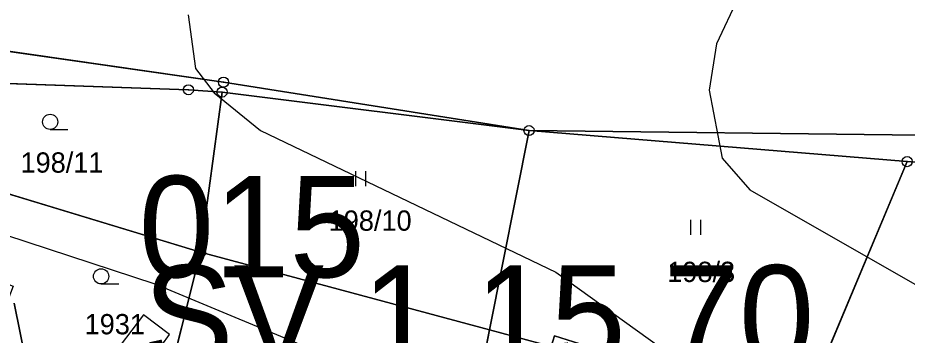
# Model space of a CAD drawing. Extents: x -706130 to -698555, y -971544 to -967260.
# Drawn here: x -703723 to -703635.3, y -970324.1 to -970292.8 of the extents above; entities that cross this region are included whole.
import ezdxf

# ---------------------------------------------------------------- set-up
doc = ezdxf.new("R2010")
doc.units = 0
for name, color, linetype in [('_Doplněk budov pro zastavěnost', 7, 'Continuous'), ('BPEJ hranice S', 7, 'Continuous'), ('Docházková izochrona - VLAK N', 7, 'Continuous'), ('Hranice intravilán', 7, 'Continuous'), ('KN_Hranice_parcel', 7, 'Continuous'), ('KN_Parcelni cisla', 7, 'Continuous'), ('KN_Polygon parcely', 7, 'Continuous'), ('KN_POZEMKY_10_LESNI POZEMEK', 7, 'Continuous'), ('KN_POZEMKY_14_OSTATNI PLOCHA', 7, 'Continuous'), ('KN_POZEMKY_5_ZAHRADA', 7, 'Continuous'), ('KN_POZEMKY_7_TTP', 7, 'Continuous'), ('KN_VYUZITI_17_ostatni plocha_ostatni komunikace', 7, 'Continuous'), ('KN_Značky bodu BP', 7, 'Continuous'), ('KN_Značky kultur', 7, 'Continuous'), ('Plochy lesní všeobecné S', 7, 'Continuous'), ('Plochy smíšené nezastavěného území všeobecné S', 7, 'Continuous'), ('Plochy smíšené obytné venkovské S', 7, 'Continuous'), ('Regulační bloky v krajině S', 7, 'Continuous'), ('Regulační bloky zastavěné S', 7, 'Continuous'), ('Regulační bloky_číslo S NEZAPINAT', 7, 'Continuous'), ('Regulační kódy zastavěné S', 7, 'Continuous'), ('VÝŠKOPIS_vrstevnice hlavní', 7, 'Continuous'), ('Zastavene uzemi N', 7, 'Continuous'), ('Zastavene uzemi plochy N', 7, 'Continuous')]:
    doc.layers.add(name, color=color, linetype=linetype)

msp = doc.modelspace()

# ---------------------------------------------------------------- linework, layer by layer
at = {"layer": '_Doplněk budov pro zastavěnost'}
msp.add_line((-703711.358, -970328.612), (-703708.082, -970324.03), dxfattribs=at)
msp.add_lwpolyline([(-703708.082, -970324.03), (-703710.648, -970322.082), (-703714.088, -970326.612)], dxfattribs=at)
at = {"layer": 'BPEJ hranice S'}
for points in [[(-703738.09, -970298.78), (-703706.21, -970299.88), (-703702.89, -970300.11), (-703672.63, -970303.91), (-703635.35, -970306.97), (-703646.15, -970332.73), (-703632.252, -970340.643)], [(-703632.252, -970340.643), (-703646.15, -970332.73), (-703635.35, -970306.97), (-703672.63, -970303.91), (-703702.89, -970300.11), (-703706.21, -970299.88), (-703738.09, -970298.78)], [(-703724.808, -970348.497), (-703721.895, -970339.494), (-703722.086, -970331.681), (-703722.192, -970327.348), (-703722.205, -970326.79), (-703723.373, -970320.95)], [(-703723.373, -970320.95), (-703722.205, -970326.79), (-703722.192, -970327.348), (-703722.086, -970331.681), (-703721.895, -970339.494), (-703724.808, -970348.497)]]:
    msp.add_lwpolyline(points, dxfattribs=at)
at = {"layer": 'Docházková izochrona - VLAK N'}
msp.add_circle((-704165.451, -969778.767), 800, dxfattribs=at)
at = {"layer": 'Hranice intravilán'}
msp.add_lwpolyline([(-703631.45, -970341.1), (-703646.15, -970332.73), (-703648.8, -970331.89), (-703654.16, -970330.19), (-703653.88, -970329.3), (-703670.11, -970324.16), (-703670.44, -970325.21), (-703676.52, -970323.58), (-703679.36, -970337.91), (-703708.75, -970330.82), (-703705.03, -970315.92), (-703739.49, -970305.44), (-703738.09, -970298.78), (-703775.52, -970299.64)], dxfattribs=at)
at = {"layer": 'KN_Hranice_parcel'}
for p, q in [((-703672.63, -970303.91), (-703702.74, -970299.14)), ((-703702.89, -970300.11), (-703705.03, -970315.92)), ((-703672.63, -970303.91), (-703702.89, -970300.11)), ((-703672.63, -970303.91), (-703676.52, -970323.58)), ((-703635.35, -970306.97), (-703672.63, -970303.91)), ((-703739.49, -970305.44), (-703705.03, -970315.92)), ((-703646.15, -970332.73), (-703635.35, -970306.97)), ((-703705.03, -970315.92), (-703708.75, -970330.82)), ((-703705.03, -970315.92), (-703676.52, -970323.58)), ((-703676.52, -970323.58), (-703679.36, -970337.91)), ((-703676.52, -970323.58), (-703670.44, -970325.21))]:
    msp.add_line(p, q, dxfattribs=at)
for points in [[(-703702.74, -970299.14), (-703733.34, -970294.74), (-703763.35, -970295.57), (-703799.54, -970296.87)], [(-703702.89, -970300.11), (-703706.21, -970299.88), (-703738.09, -970298.78)], [(-703623.56, -970304.51), (-703634.06, -970304.37), (-703672.63, -970303.91)], [(-703526.62, -970376.37), (-703586.2, -970324.53), (-703627.08, -970307.65), (-703635.35, -970306.97)]]:
    msp.add_lwpolyline(points, dxfattribs=at)
at = {"layer": 'KN_Polygon parcely'}
for points in [[(-703575.83, -970307.17), (-703543.88, -970308.96), (-703519.13, -970313.02), (-703534.02, -970307.63), (-703565.14, -970278.41), (-703570.06, -970274.88), (-703590.14, -970267.18), (-703599.73, -970265.63), (-703609.71, -970264.02), (-703624.74, -970265.74), (-703731.89, -970278.02), (-703810.39, -970283.01), (-703832.17, -970298.91), (-703799.54, -970296.87), (-703763.35, -970295.57), (-703733.34, -970294.74), (-703702.74, -970299.14), (-703672.63, -970303.91), (-703634.06, -970304.37), (-703623.56, -970304.51)], [(-703832.17, -970298.91), (-703833.56, -970299.93), (-703832.7, -970301.24), (-703809.34, -970300.42), (-703775.52, -970299.64), (-703738.09, -970298.78), (-703706.21, -970299.88), (-703702.89, -970300.11), (-703672.63, -970303.91), (-703702.74, -970299.14), (-703733.34, -970294.74), (-703763.35, -970295.57), (-703799.54, -970296.87)], [(-703739.49, -970305.44), (-703705.03, -970315.92), (-703702.89, -970300.11), (-703706.21, -970299.88), (-703738.09, -970298.78)], [(-703702.89, -970300.11), (-703705.03, -970315.92), (-703676.52, -970323.58), (-703672.63, -970303.91)], [(-703646.15, -970332.73), (-703635.35, -970306.97), (-703672.63, -970303.91), (-703676.52, -970323.58), (-703670.44, -970325.21), (-703670.11, -970324.16), (-703653.88, -970329.3), (-703654.16, -970330.19), (-703648.8, -970331.89)], [(-703634.06, -970304.37), (-703672.63, -970303.91), (-703635.35, -970306.97), (-703627.08, -970307.65), (-703586.2, -970324.53), (-703526.62, -970376.37), (-703520.6, -970377.03), (-703567.84, -970335.32), (-703584.36, -970321.95), (-703623.56, -970304.51)], [(-703708.75, -970330.82), (-703705.03, -970315.92), (-703739.49, -970305.44), (-703743.13, -970318.6), (-703744, -970321.72), (-703741.07, -970322.48), (-703739.71, -970319.1), (-703737.59, -970313.85), (-703723.5, -970319.27), (-703725.62, -970324.78), (-703726.21, -970326.31)], [(-703625.56, -970327.91), (-703593.92, -970335.61), (-703602.16, -970353.21), (-703568.92, -970363.91), (-703550.58, -970370.54), (-703536.13, -970374.49), (-703526.62, -970376.37), (-703586.2, -970324.53), (-703627.08, -970307.65), (-703635.35, -970306.97), (-703646.15, -970332.73), (-703631.45, -970341.1)], [(-703708.75, -970330.82), (-703679.36, -970337.91), (-703676.52, -970323.58), (-703705.03, -970315.92)], [(-703679.36, -970337.91), (-703648.37, -970348.91), (-703639.36, -970354.95), (-703637.01, -970347.57), (-703646.15, -970332.73), (-703648.8, -970331.89), (-703649.55, -970334.26), (-703651.62, -970340.78), (-703673.2, -970333.94), (-703670.44, -970325.21), (-703676.52, -970323.58)]]:
    msp.add_lwpolyline(points, close=True, dxfattribs=at)
at = {"layer": 'KN_POZEMKY_10_LESNI POZEMEK'}
for p, q in [((-703733.34, -970294.74), (-703702.74, -970299.14)), ((-703702.74, -970299.14), (-703733.34, -970294.74)), ((-703706.21, -970299.88), (-703738.09, -970298.78)), ((-703702.74, -970299.14), (-703672.63, -970303.91)), ((-703672.63, -970303.91), (-703702.74, -970299.14)), ((-703702.89, -970300.11), (-703706.21, -970299.88)), ((-703672.63, -970303.91), (-703702.89, -970300.11)), ((-703634.06, -970304.37), (-703672.63, -970303.91)), ((-703646.15, -970332.73), (-703635.35, -970306.97)), ((-703635.35, -970306.97), (-703627.08, -970307.65))]:
    msp.add_line(p, q, dxfattribs=at)
at = {"layer": 'KN_POZEMKY_14_OSTATNI PLOCHA'}
for p, q in [((-703635.35, -970306.97), (-703672.63, -970303.91)), ((-703672.63, -970303.91), (-703634.06, -970304.37)), ((-703627.08, -970307.65), (-703635.35, -970306.97))]:
    msp.add_line(p, q, dxfattribs=at)
at = {"layer": 'KN_POZEMKY_5_ZAHRADA'}
for p, q in [((-703738.09, -970298.78), (-703706.21, -970299.88)), ((-703706.21, -970299.88), (-703702.89, -970300.11)), ((-703702.89, -970300.11), (-703705.03, -970315.92)), ((-703705.03, -970315.92), (-703739.49, -970305.44)), ((-703739.49, -970305.44), (-703705.03, -970315.92)), ((-703705.03, -970315.92), (-703708.75, -970330.82))]:
    msp.add_line(p, q, dxfattribs=at)
at = {"layer": 'KN_POZEMKY_7_TTP'}
for p, q in [((-703705.03, -970315.92), (-703702.89, -970300.11)), ((-703702.89, -970300.11), (-703672.63, -970303.91)), ((-703672.63, -970303.91), (-703676.52, -970323.58)), ((-703676.52, -970323.58), (-703672.63, -970303.91)), ((-703672.63, -970303.91), (-703635.35, -970306.97)), ((-703635.35, -970306.97), (-703646.15, -970332.73)), ((-703708.75, -970330.82), (-703705.03, -970315.92)), ((-703676.52, -970323.58), (-703705.03, -970315.92)), ((-703705.03, -970315.92), (-703676.52, -970323.58)), ((-703679.36, -970337.91), (-703676.52, -970323.58)), ((-703676.52, -970323.58), (-703679.36, -970337.91)), ((-703676.52, -970323.58), (-703670.44, -970325.21)), ((-703670.44, -970325.21), (-703676.52, -970323.58))]:
    msp.add_line(p, q, dxfattribs=at)
at = {"layer": 'KN_VYUZITI_17_ostatni plocha_ostatni komunikace'}
for p, q in [((-703635.35, -970306.97), (-703672.63, -970303.91)), ((-703672.63, -970303.91), (-703634.06, -970304.37)), ((-703627.08, -970307.65), (-703635.35, -970306.97))]:
    msp.add_line(p, q, dxfattribs=at)
at = {"layer": 'KN_Značky bodu BP'}
for centre, radius in [((-703702.74, -970299.14), 0.5), ((-703706.21, -970299.88), 0.5), ((-703706.21, -970299.88), 0.0303), ((-703702.89, -970300.11), 0.5), ((-703702.74, -970299.14), 0.0303), ((-703702.89, -970300.11), 0.0303), ((-703672.63, -970303.91), 0.5), ((-703672.63, -970303.91), 0.0303), ((-703635.35, -970306.97), 0.5), ((-703635.35, -970306.97), 0.0303), ((-703705.03, -970315.92), 0.5), ((-703705.03, -970315.92), 0.0303)]:
    msp.add_circle(centre, radius, dxfattribs=at)
at = {"layer": 'KN_Značky kultur'}
for p, q in [((-703719.833, -970303.8), (-703718.083, -970303.8)), ((-703689.701, -970309.4), (-703689.701, -970307.9)), ((-703688.7, -970309.4), (-703688.7, -970307.9)), ((-703656.691, -970314.21), (-703656.691, -970312.71)), ((-703655.69, -970314.21), (-703655.69, -970312.71)), ((-703714.813, -970319.04), (-703713.063, -970319.04))]:
    msp.add_line(p, q, dxfattribs=at)
for centre in [(-703719.833, -970303.05), (-703714.813, -970318.29)]:
    msp.add_circle(centre, 0.75, dxfattribs=at)
at = {"layer": 'Plochy lesní všeobecné S'}
for p, q in [((-703738.09, -970298.78), (-703706.21, -970299.88)), ((-703706.21, -970299.88), (-703702.89, -970300.11)), ((-703702.89, -970300.11), (-703672.63, -970303.91)), ((-703672.63, -970303.91), (-703634.06, -970304.37)), ((-703635.35, -970306.97), (-703646.15, -970332.73)), ((-703627.08, -970307.65), (-703635.35, -970306.97))]:
    msp.add_line(p, q, dxfattribs=at)
at = {"layer": 'Plochy smíšené nezastavěného území všeobecné S'}
msp.add_line((-703635.35, -970306.97), (-703627.08, -970307.65), dxfattribs=at)
msp.add_lwpolyline([(-703623.56, -970304.51), (-703634.06, -970304.37), (-703672.63, -970303.91), (-703635.35, -970306.97)], dxfattribs=at)
at = {"layer": 'Plochy smíšené obytné venkovské S'}
for p, q in [((-703706.21, -970299.88), (-703738.09, -970298.78)), ((-703702.89, -970300.11), (-703706.21, -970299.88)), ((-703672.63, -970303.91), (-703702.89, -970300.11)), ((-703635.35, -970306.97), (-703672.63, -970303.91)), ((-703646.15, -970332.73), (-703635.35, -970306.97))]:
    msp.add_line(p, q, dxfattribs=at)
at = {"layer": 'Regulační bloky v krajině S'}
for p, q in [((-703738.09, -970298.78), (-703706.21, -970299.88)), ((-703706.21, -970299.88), (-703702.89, -970300.11)), ((-703702.89, -970300.11), (-703672.63, -970303.91)), ((-703672.63, -970303.91), (-703634.06, -970304.37)), ((-703635.35, -970306.97), (-703646.15, -970332.73)), ((-703627.08, -970307.65), (-703635.35, -970306.97)), ((-703635.35, -970306.97), (-703627.08, -970307.65))]:
    msp.add_line(p, q, dxfattribs=at)
msp.add_lwpolyline([(-703623.56, -970304.51), (-703634.06, -970304.37), (-703672.63, -970303.91), (-703635.35, -970306.97)], dxfattribs=at)
at = {"layer": 'Regulační bloky zastavěné S'}
for p, q in [((-703706.21, -970299.88), (-703738.09, -970298.78)), ((-703702.89, -970300.11), (-703706.21, -970299.88)), ((-703672.63, -970303.91), (-703702.89, -970300.11)), ((-703635.35, -970306.97), (-703672.63, -970303.91)), ((-703646.15, -970332.73), (-703635.35, -970306.97))]:
    msp.add_line(p, q, dxfattribs=at)
at = {"layer": 'VÝŠKOPIS_vrstevnice hlavní'}
for points in [[(-703756.021, -970289.924), (-703756.021, -970293.348), (-703754.451, -970297.914), (-703749.03, -970303.906), (-703745.464, -970306.474), (-703736.903, -970310.04), (-703709.511, -970319.029), (-703692.39, -970326.163), (-703670.133, -970337.148), (-703652.87, -970347.706), (-703628.759, -970365.539)], [(-703652.014, -970290.78), (-703654.154, -970295.346), (-703654.868, -970299.911), (-703653.584, -970306.617), (-703650.873, -970309.755), (-703633.895, -970319.457), (-703598.512, -970343.283), (-703566.982, -970368.25), (-703547.294, -970385.513), (-703536.736, -970395.786), (-703526.607, -970407.199), (-703515.906, -970420.896), (-703487.515, -970468.833), (-703454.558, -970530.467), (-703434.299, -970564.708), (-703416.75, -970589.818), (-703387.788, -970624.059)], [(-703706.229, -970292.492), (-703705.515, -970297.771), (-703703.661, -970300.196), (-703699.095, -970303.906), (-703669.99, -970317.887), (-703650.73, -970331.726), (-703611.924, -970355.553)]]:
    msp.add_lwpolyline(points, dxfattribs=at)
at = {"layer": 'Zastavene uzemi N'}
msp.add_lwpolyline([(-703631.45, -970341.1), (-703646.15, -970332.73), (-703635.35, -970306.97), (-703672.63, -970303.91), (-703702.89, -970300.11), (-703706.21, -970299.88), (-703738.09, -970298.78), (-703775.52, -970299.64)], dxfattribs=at)
at = {"layer": 'Zastavene uzemi plochy N'}
msp.add_lwpolyline([(-703631.45, -970341.1), (-703646.15, -970332.73), (-703635.35, -970306.97), (-703672.63, -970303.91), (-703702.89, -970300.11), (-703706.21, -970299.88), (-703738.09, -970298.78), (-703775.52, -970299.64)], dxfattribs=at)

# ---------------------------------------------------------------- texts
at = {"layer": 'KN_Parcelni cisla'}
for s, p in [('198/11', (-703722.76, -970308.059)), ('198/10', (-703692.38, -970313.789)), ('198/3', (-703659, -970318.85)), ('1931', (-703716.44, -970324.01))]:
    msp.add_text(s, height=2, dxfattribs=at).set_placement(p)
at = {"layer": 'Regulační bloky_číslo S NEZAPINAT'}
msp.add_text('015', height=10, dxfattribs=at).set_placement((-703711.113, -970318.377))
at = {"layer": 'Regulační kódy zastavěné S'}
msp.add_text('SV.1.15.70', height=10, dxfattribs=at).set_placement((-703710.666, -970327.191))

doc.saveas('drawing.dxf')
